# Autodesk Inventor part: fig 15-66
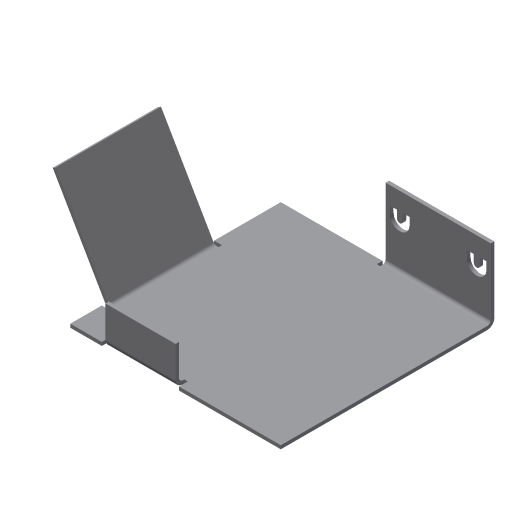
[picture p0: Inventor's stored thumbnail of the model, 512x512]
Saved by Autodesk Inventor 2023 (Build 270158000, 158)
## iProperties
Created: 2002-04
Part Number: fig 15-66
Document SubType Name: Sheet Metal
Density: 1 g/cm^3
Sheet Metal Rule: Default
Material: Generic
Appearance: Default
Control State: 0
Master: False
Checked Out: False
Shininess: 77.0
Angle Display Precision: 2
Document Length Units: 11269
Document Angle Units: 11279
Document Time Units: 11290
Document Mass Units: 11283
Document Length Units Precision: 3
Document Angle Units Precision: 2
Density: 0.0
Volumn: 0.0
Area: 0.0
PropertySet Name: Model Information
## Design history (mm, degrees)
node "Face1"
  sketch "Sketch1"
    geometry: L1 (12.647, 25.882)-(12.647, -14.118); L2 (12.647, -14.118)-(-17.353, -14.118); L3 (-17.353, -14.118)-(-17.353, 15.882); L4 (-17.353, 15.882)-(-2.353, 15.882); L5 (-2.353, 15.882)-(-2.353, 25.882); L6 (-2.353, 25.882)-(12.647, 25.882); 1 further point
    constraints: 12 end point, 4 parallel, 1 perpendicular
    dimensions: "d5" = 30 distance of L2.end L3.end; "d6" = 10 distance of L4.end L5.end; "d7" = 15 distance of L3.end L4.end; "d25" = 15 distance of L5.end L1.start
sketch "Sketch3"
  geometry: L1 (10, -15)-(10, 0)
  constraints: 2 end point
feature "Fold3" sketch "Sketch3" dims "d26" = 0.5 (= BendRadius), "d27" = 90 deg, "d28" = 0.5 (= BendRadius), "d96" = 0.5 (= BendReliefWidth), "d97" = 0.25 (= BendReliefDepth), "d98" = 1 (= MinimumRemnant), "d107" = 0.5 (= Thickness), "SeamGap" = 0.01
node "Flange2"
sketch "Sketch6"
  geometry: L1 (-6.914, 3.413)-(-5.843, 3.413); L2 (-5.843, 0.624)-(-6.914, 0.624); L3 (-6.914, 2.432)-(-5.843, 2.432); L4 (-5.843, 1.605)-(-6.914, 1.605); L5 (-6.914, 0.624)-(-6.914, 1.605); L6 (-6.914, 2.432)-(-6.914, 3.413); L7 (-6.914, 12.568)-(-6.914, 11.587); L8 (-6.914, 14.376)-(-6.914, 13.395); L9 (-6.914, 11.587)-(-5.843, 11.587); L10 (-5.843, 14.376)-(-6.914, 14.376); L11 (-6.914, 12.568)-(-5.843, 12.568); L12 (-5.843, 13.395)-(-6.914, 13.395); A1 r 1.394 centre (-5.843, 2.018) between (-5.843, 0.624) and (-5.843, 3.413); A2 r 0.413 centre (-5.843, 2.018) between (-5.843, 1.605) and (-5.843, 2.432); A3 r 1.394 centre (-5.843, 12.982) between (-5.843, 11.587) and (-5.843, 14.376); A4 r 0.413 centre (-5.843, 12.982) between (-5.843, 12.568) and (-5.843, 13.395)
  constraints: 24 end point, 8 point on circle, 4 centre point, 3 equal length, 1 perpendicular
cut "Cut1" sketch "Sketch6" dims "d49" = 0.5 (= Thickness), "d50" = 0
node "Flange3"
body "Solid1"
face "Plate1" dims "d107" = 0.5 (= Thickness)
sketch "Sketch5"
  geometry: L1 (20, 0)-(5, 0); L2 (5, 0)-(5, 15); L3 (5, 15)-(20, 15); L4 (20, 15)-(20, 0)
  constraints: 8 end point
face "Plate6" dims "d35" = 10, "d36" = 5, "d38" = 15, "d39" = 60 deg, "d40" = 0.5 (= BendRadius), "d107" = 0.5 (= Thickness), "MinimumRemnant" = 1 (= 2 x Thickness), "BendReliefWidth" = 0.5 (= Thickness)
bend "Bend5" dims "d38" = 15, "d39" = 60 deg, "d40" = 0.5 (= BendRadius), "d99" = 0.5 (= BendReliefWidth), "d100" = 0.25 (= BendReliefDepth), "d101" = 1 (= MinimumRemnant), "d107" = 0.5 (= Thickness), "SeamGap" = 0.01, "MinimumRemnant" = 1 (= 2 x Thickness), "BendReliefWidth" = 0.5 (= Thickness), "TransitionRadius" = 0.5 (= BendRadius)
sketch "Sketch7"
  geometry: L1 (25, 0)-(15, 0); L2 (15, 0)-(15, 5); L3 (15, 5)-(25, 5); L4 (25, 5)-(25, 0)
  constraints: 8 end point
face "Plate7" dims "d57" = 5, "d58" = 10, "d60" = 5, "d61" = 90 deg, "d62" = 0.5 (= BendRadius), "d107" = 0.5 (= Thickness), "MinimumRemnant" = 1 (= 2 x Thickness), "BendReliefWidth" = 0.5 (= Thickness)
bend "Bend7" dims "d59" = 0.5 (= BendRadius), "d60" = 5, "d61" = 90 deg, "d62" = 0.5 (= BendRadius), "d102" = 0.5 (= BendReliefWidth), "d103" = 0.25 (= BendReliefDepth), "d104" = 1 (= MinimumRemnant), "d107" = 0.5 (= Thickness), "SeamGap" = 0.01, "MinimumRemnant" = 1 (= 2 x Thickness), "BendReliefWidth" = 0.5 (= Thickness)
other parameters: "Thickness" = 0.5, "BendRadius" = 0.5 (= Thickness), "BendReliefDepth" = 0.25 (= 0.5 x Thickness), "CornerReliefSize" = 2 (= 4 x Thickness), "d0" = 0.5 (= BendRadius), "d13" = 0.5 (= BendRadius), "d31" = 0.5 (= BendRadius), "d37" = 0.5 (= BendRadius), "JacobiRadiusSize" = 0.5 (= Thickness), "GapSize" = 0.5 (= Thickness)
